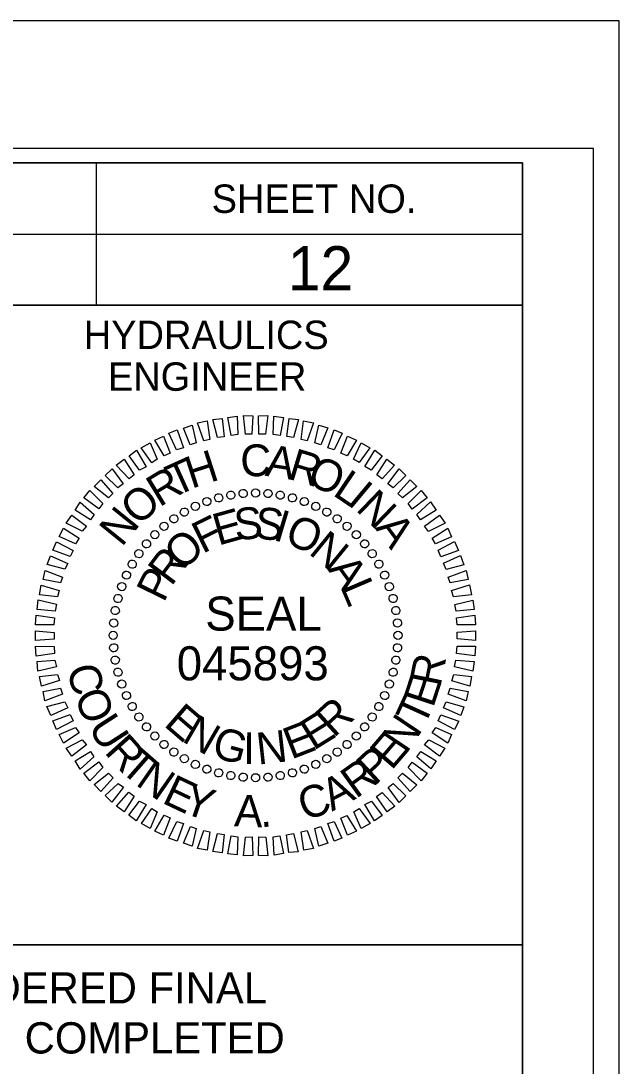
# Model space of a CAD drawing. Extents: x 1628636 to 1631253, y 896159 to 897520.
# Drawn here: x 1630638.2 to 1630743.5, y 897075 to 897258.9 of the extents above; entities that cross this region are included whole.
import ezdxf

# ---------------------------------------------------------------- set-up
doc = ezdxf.new("R2010")
doc.units = 0
for name, color, linetype in [('Default', 7, 'Continuous'), ('Sheet Cutting Line CELL', 7, 'Continuous'), ('Sheet Data Field CELL', 7, 'Continuous'), ('Sheet Plot Border Inside CELL', 7, 'Continuous'), ('Sheet Plot Border Outside CELL', 7, 'Continuous'), ('Sheet Profile CELL', 7, 'Continuous'), ('Sheet Profile Grid Major CELL', 7, 'Continuous'), ('Sheet Sticker Exception Certification CELL', 7, 'Continuous')]:
    doc.layers.add(name, color=color, linetype=linetype)

msp = doc.modelspace()

# ---------------------------------------------------------------- linework, layer by layer
at = {"layer": 'Default'}
for p, q in [((1630673.04, 897174.95), (1630673.04, 897174.95)), ((1630675.19, 897175.4), (1630675.19, 897175.4)), ((1630677.34, 897175.7), (1630677.34, 897175.7)), ((1630679.54, 897175.85), (1630679.54, 897175.85)), ((1630681.74, 897175.7), (1630681.74, 897175.7)), ((1630683.89, 897175.4), (1630683.89, 897175.4)), ((1630686.04, 897174.95), (1630686.04, 897174.95)), ((1630668.99, 897173.45), (1630668.99, 897173.45)), ((1630670.94, 897174.3), (1630670.94, 897174.3)), ((1630688.14, 897174.3), (1630688.14, 897174.3)), ((1630690.14, 897173.45), (1630690.14, 897173.45)), ((1630665.19, 897171.25), (1630665.19, 897171.25)), ((1630667.04, 897172.45), (1630667.04, 897172.45)), ((1630692.09, 897172.45), (1630692.09, 897172.45)), ((1630693.89, 897171.3), (1630693.89, 897171.3)), ((1630663.39, 897170), (1630663.39, 897170)), ((1630695.69, 897169.95), (1630695.69, 897169.95)), ((1630661.79, 897168.45), (1630661.79, 897168.45)), ((1630697.24, 897168.5), (1630697.24, 897168.5)), ((1630660.29, 897166.9), (1630660.29, 897166.9)), ((1630698.79, 897166.85), (1630698.79, 897166.85)), ((1630658.99, 897165.1), (1630658.99, 897165.1)), ((1630700.04, 897165.1), (1630700.04, 897165.1)), ((1630657.79, 897163.25), (1630657.79, 897163.25)), ((1630701.24, 897163.25), (1630701.24, 897163.25)), ((1630656.79, 897161.3), (1630656.79, 897161.3)), ((1630702.24, 897161.3), (1630702.24, 897161.3)), ((1630655.94, 897159.3), (1630655.94, 897159.3)), ((1630703.09, 897159.3), (1630703.09, 897159.3)), ((1630655.29, 897157.25), (1630655.29, 897157.25)), ((1630703.74, 897157.25), (1630703.74, 897157.25)), ((1630654.84, 897155.1), (1630654.84, 897155.1)), ((1630704.19, 897155.05), (1630704.19, 897155.05)), ((1630654.54, 897152.95), (1630654.54, 897152.95)), ((1630704.49, 897152.9), (1630704.49, 897152.9)), ((1630654.44, 897150.75), (1630654.44, 897150.75)), ((1630704.64, 897150.7), (1630704.64, 897150.7)), ((1630654.59, 897148.55), (1630654.59, 897148.55)), ((1630704.54, 897148.5), (1630704.54, 897148.5)), ((1630654.89, 897146.4), (1630654.89, 897146.4)), ((1630704.24, 897146.4), (1630704.24, 897146.4)), ((1630655.34, 897144.25), (1630655.34, 897144.25)), ((1630703.74, 897144.2), (1630703.74, 897144.2)), ((1630655.99, 897142.15), (1630655.99, 897142.15)), ((1630703.09, 897142.15), (1630703.09, 897142.15)), ((1630656.84, 897140.15), (1630656.84, 897140.15)), ((1630702.29, 897140.15), (1630702.29, 897140.15)), ((1630657.84, 897138.2), (1630657.84, 897138.2)), ((1630701.29, 897138.2), (1630701.29, 897138.2)), ((1630659.04, 897136.35), (1630659.04, 897136.35)), ((1630700.09, 897136.35), (1630700.09, 897136.35)), ((1630660.29, 897134.6), (1630660.29, 897134.6)), ((1630698.74, 897134.6), (1630698.74, 897134.6)), ((1630661.79, 897133), (1630661.79, 897133)), ((1630697.29, 897133), (1630697.29, 897133)), ((1630663.39, 897131.5), (1630663.39, 897131.5)), ((1630695.64, 897131.5), (1630695.64, 897131.5)), ((1630665.14, 897130.2), (1630665.14, 897130.2)), ((1630666.99, 897129), (1630666.99, 897129)), ((1630692.09, 897129), (1630692.09, 897129)), ((1630693.89, 897130.25), (1630693.89, 897130.25)), ((1630668.94, 897128), (1630668.94, 897128)), ((1630670.94, 897127.15), (1630670.94, 897127.15)), ((1630688.09, 897127.15), (1630688.09, 897127.15)), ((1630690.09, 897128), (1630690.09, 897128)), ((1630673.04, 897126.5), (1630673.04, 897126.5)), ((1630675.19, 897126.05), (1630675.19, 897126.05)), ((1630677.34, 897125.75), (1630677.34, 897125.75)), ((1630679.49, 897125.65), (1630679.49, 897125.65)), ((1630681.69, 897125.8), (1630681.69, 897125.8)), ((1630683.89, 897126.05), (1630683.89, 897126.05)), ((1630686.04, 897126.5), (1630686.04, 897126.5))]:
    msp.add_line(p, q, dxfattribs=at)
for points in [[(1630668.04, 897184.3), (1630666.84, 897187.25), (1630668.39, 897187.75), (1630669.09, 897184.65)], [(1630670.44, 897185), (1630669.34, 897188.15), (1630671.04, 897188.5), (1630671.49, 897185.25)], [(1630672.84, 897185.6), (1630671.99, 897188.75), (1630673.64, 897188.95), (1630674.04, 897185.7)], [(1630675.24, 897185.95), (1630674.64, 897189.1), (1630676.29, 897189.35), (1630676.44, 897186.1)], [(1630677.74, 897186.2), (1630677.39, 897189.45), (1630679.04, 897189.4), (1630678.89, 897186.2)], [(1630680.09, 897186.2), (1630680.04, 897189.4), (1630681.69, 897189.45), (1630681.29, 897186.2)], [(1630682.64, 897186.1), (1630682.74, 897189.35), (1630684.44, 897189.1), (1630683.84, 897185.95)], [(1630685.04, 897185.75), (1630685.44, 897188.95), (1630687.09, 897188.75), (1630686.24, 897185.6)], [(1630687.59, 897185.25), (1630687.99, 897188.5), (1630689.74, 897188.15), (1630688.64, 897185)], [(1630689.99, 897184.65), (1630690.64, 897187.75), (1630692.24, 897187.3), (1630691.04, 897184.3)], [(1630663.44, 897182.35), (1630661.79, 897185.15), (1630663.34, 897185.85), (1630664.54, 897182.85)], [(1630665.64, 897183.45), (1630664.29, 897186.35), (1630665.74, 897186.95), (1630666.84, 897183.8)], [(1630692.24, 897183.8), (1630693.34, 897186.95), (1630694.79, 897186.35), (1630693.39, 897183.45)], [(1630694.54, 897182.85), (1630695.69, 897185.85), (1630697.29, 897185.15), (1630695.64, 897182.35)], [(1630661.29, 897181.15), (1630659.39, 897183.8), (1630660.99, 897184.65), (1630662.24, 897181.75)], [(1630696.79, 897181.75), (1630698.09, 897184.65), (1630699.64, 897183.8), (1630697.79, 897181.2)], [(1630659.14, 897179.85), (1630657.29, 897182.35), (1630658.59, 897183.35), (1630660.29, 897180.45)], [(1630698.79, 897180.5), (1630700.54, 897183.35), (1630701.84, 897182.35), (1630699.89, 897179.85)], [(1630657.29, 897178.3), (1630655.04, 897180.7), (1630656.39, 897181.75), (1630658.19, 897179)], [(1630700.89, 897179), (1630702.64, 897181.75), (1630703.99, 897180.7), (1630701.84, 897178.3)], [(1630655.29, 897176.75), (1630653.09, 897178.9), (1630654.29, 897180.1), (1630656.24, 897177.45)], [(1630702.79, 897177.45), (1630704.79, 897180.1), (1630705.99, 897178.9), (1630703.74, 897176.75)], [(1630653.69, 897174.95), (1630651.14, 897176.95), (1630652.34, 897178.15), (1630654.44, 897175.75)], [(1630704.59, 897175.75), (1630706.74, 897178.15), (1630707.94, 897176.95), (1630705.39, 897174.95)], [(1630651.99, 897173.05), (1630649.34, 897174.95), (1630650.39, 897176.25), (1630652.69, 897173.95)], [(1630706.39, 897173.95), (1630708.69, 897176.25), (1630709.74, 897174.95), (1630707.09, 897173)], [(1630650.49, 897171.1), (1630647.79, 897172.8), (1630648.69, 897174.2), (1630651.14, 897172.05)], [(1630707.94, 897172.05), (1630710.34, 897174.25), (1630711.29, 897172.8), (1630708.54, 897171.1)], [(1630649.04, 897169.1), (1630646.24, 897170.5), (1630647.19, 897171.95), (1630649.79, 897170)], [(1630709.24, 897170), (1630711.89, 897171.95), (1630712.89, 897170.5), (1630709.99, 897169.05)], [(1630647.84, 897166.9), (1630644.99, 897168.15), (1630645.74, 897169.65), (1630648.49, 897167.85)], [(1630710.59, 897167.9), (1630713.34, 897169.65), (1630714.04, 897168.1), (1630711.19, 897166.9)], [(1630646.94, 897164.65), (1630643.84, 897165.75), (1630644.54, 897167.25), (1630647.44, 897165.7)], [(1630711.64, 897165.75), (1630714.54, 897167.3), (1630715.24, 897165.7), (1630712.14, 897164.6)], [(1630645.99, 897162.4), (1630642.89, 897163.25), (1630643.44, 897164.75), (1630646.49, 897163.4)], [(1630712.59, 897163.45), (1630715.59, 897164.8), (1630716.19, 897163.2), (1630713.09, 897162.35)], [(1630645.24, 897160), (1630642.14, 897160.6), (1630642.49, 897162.2), (1630645.59, 897161)], [(1630713.44, 897161), (1630716.59, 897162.2), (1630716.94, 897160.6), (1630713.79, 897160)], [(1630644.69, 897157.55), (1630641.54, 897157.9), (1630641.84, 897159.6), (1630644.99, 897158.65)], [(1630714.04, 897158.65), (1630717.19, 897159.65), (1630717.54, 897157.9), (1630714.39, 897157.55)], [(1630644.29, 897155.05), (1630641.09, 897155.3), (1630641.29, 897157), (1630644.54, 897156.25)], [(1630714.59, 897156.2), (1630717.79, 897156.95), (1630717.99, 897155.3), (1630714.84, 897155.05)], [(1630644.04, 897152.6), (1630640.79, 897152.6), (1630640.94, 897154.3), (1630644.14, 897153.85)], [(1630714.89, 897153.85), (1630718.14, 897154.35), (1630718.24, 897152.65), (1630714.99, 897152.65)], [(1630644.09, 897150.1), (1630640.84, 897149.85), (1630640.79, 897151.55), (1630644.09, 897151.3)], [(1630714.99, 897151.35), (1630718.24, 897151.6), (1630718.24, 897149.9), (1630714.99, 897150.15)], [(1630644.14, 897147.6), (1630640.94, 897147.1), (1630640.84, 897148.85), (1630644.09, 897148.8)], [(1630714.99, 897148.85), (1630718.24, 897148.85), (1630718.14, 897147.15), (1630714.89, 897147.6)], [(1630644.54, 897145.25), (1630641.24, 897144.45), (1630641.09, 897146.15), (1630644.24, 897146.4)], [(1630714.79, 897146.4), (1630717.99, 897146.15), (1630717.79, 897144.5), (1630714.54, 897145.25)], [(1630645.04, 897142.85), (1630641.89, 897141.85), (1630641.54, 897143.55), (1630644.69, 897143.9)], [(1630714.44, 897143.9), (1630717.54, 897143.55), (1630717.24, 897141.85), (1630714.09, 897142.8)], [(1630645.59, 897140.45), (1630642.44, 897139.25), (1630642.14, 897140.9), (1630645.24, 897141.5)], [(1630713.79, 897141.5), (1630716.94, 897140.9), (1630716.59, 897139.25), (1630713.44, 897140.45)], [(1630646.49, 897138), (1630643.49, 897136.65), (1630642.84, 897138.25), (1630645.99, 897139.1)], [(1630713.09, 897139.05), (1630716.19, 897138.2), (1630715.64, 897136.7), (1630712.59, 897138.05)], [(1630647.44, 897135.75), (1630644.49, 897134.2), (1630643.84, 897135.75), (1630646.94, 897136.85)], [(1630712.14, 897136.8), (1630715.29, 897135.7), (1630714.54, 897134.2), (1630711.64, 897135.75)], [(1630648.49, 897133.6), (1630645.74, 897131.8), (1630644.99, 897133.35), (1630647.84, 897134.55)], [(1630711.24, 897134.55), (1630714.04, 897133.35), (1630713.34, 897131.8), (1630710.59, 897133.6)], [(1630649.79, 897131.5), (1630647.19, 897129.5), (1630646.24, 897130.95), (1630649.04, 897132.4)], [(1630710.04, 897132.4), (1630712.84, 897130.95), (1630711.89, 897129.5), (1630709.29, 897131.5)], [(1630651.09, 897129.4), (1630648.69, 897127.25), (1630647.79, 897128.7), (1630650.49, 897130.35)], [(1630708.59, 897130.35), (1630711.29, 897128.7), (1630710.39, 897127.3), (1630707.94, 897129.4)], [(1630652.64, 897127.5), (1630650.39, 897125.2), (1630649.34, 897126.5), (1630651.94, 897128.5)], [(1630707.09, 897128.45), (1630709.74, 897126.5), (1630708.69, 897125.2), (1630706.39, 897127.5)], [(1630654.49, 897125.7), (1630652.29, 897123.3), (1630651.14, 897124.55), (1630653.64, 897126.5)], [(1630705.39, 897126.5), (1630707.94, 897124.5), (1630706.74, 897123.3), (1630704.59, 897125.7)], [(1630656.29, 897124.05), (1630654.24, 897121.4), (1630653.09, 897122.6), (1630655.34, 897124.7)], [(1630703.74, 897124.7), (1630705.99, 897122.55), (1630704.79, 897121.35), (1630702.84, 897124)], [(1630658.19, 897122.5), (1630656.44, 897119.75), (1630655.09, 897120.75), (1630657.24, 897123.2)], [(1630660.29, 897121), (1630658.54, 897118.15), (1630657.24, 897119.15), (1630659.14, 897121.6)], [(1630699.94, 897121.6), (1630701.79, 897119.1), (1630700.49, 897118.15), (1630698.79, 897121)], [(1630701.79, 897123.15), (1630704.04, 897120.75), (1630702.69, 897119.7), (1630700.84, 897122.45)], [(1630662.24, 897119.7), (1630660.99, 897116.8), (1630659.44, 897117.7), (1630661.29, 897120.3)], [(1630697.74, 897120.3), (1630699.69, 897117.65), (1630698.14, 897116.8), (1630696.84, 897119.7)], [(1630664.54, 897118.65), (1630663.34, 897115.6), (1630661.79, 897116.3), (1630663.44, 897119.15)], [(1630666.84, 897117.7), (1630665.74, 897114.55), (1630664.29, 897115.1), (1630665.69, 897118.05)], [(1630693.39, 897118.05), (1630694.74, 897115.1), (1630693.34, 897114.55), (1630692.24, 897117.7)], [(1630695.59, 897119.1), (1630697.29, 897116.3), (1630695.74, 897115.6), (1630694.54, 897118.6)], [(1630669.09, 897116.8), (1630668.39, 897113.7), (1630666.84, 897114.2), (1630668.09, 897117.15)], [(1630671.49, 897116.2), (1630671.04, 897113), (1630669.34, 897113.3), (1630670.44, 897116.45)], [(1630674.04, 897115.75), (1630673.64, 897112.5), (1630671.99, 897112.75), (1630672.84, 897115.9)], [(1630686.24, 897115.9), (1630687.04, 897112.7), (1630685.39, 897112.55), (1630684.99, 897115.7)], [(1630688.64, 897116.45), (1630689.74, 897113.3), (1630688.04, 897112.95), (1630687.59, 897116.2)], [(1630691.04, 897117.15), (1630692.24, 897114.2), (1630690.64, 897113.7), (1630689.94, 897116.8)], [(1630676.44, 897115.35), (1630676.29, 897112.15), (1630674.64, 897112.35), (1630675.24, 897115.5)], [(1630678.94, 897115.3), (1630679.04, 897112.05), (1630677.39, 897112), (1630677.74, 897115.25)], [(1630681.34, 897115.25), (1630681.69, 897112), (1630680.04, 897112.05), (1630680.14, 897115.3)], [(1630683.79, 897115.5), (1630684.44, 897112.4), (1630682.79, 897112.1), (1630682.64, 897115.35)]]:
    msp.add_lwpolyline(points, close=True, dxfattribs=at)
for centre, major_axis in [((1630670.97, 897174.32), (-0.246, 0.676)), ((1630673.05, 897174.98), (-0.186, 0.695)), ((1630675.19, 897175.45), (-0.125, 0.708)), ((1630677.36, 897175.74), (-0.063, 0.717)), ((1630679.54, 897175.83), (0, 0.719)), ((1630681.72, 897175.74), (0.063, 0.717)), ((1630683.89, 897175.45), (0.125, 0.708)), ((1630686.02, 897174.98), (0.186, 0.695)), ((1630688.11, 897174.32), (0.246, 0.676)), ((1630667.01, 897172.47), (-0.36, 0.623)), ((1630668.95, 897173.48), (-0.304, 0.652)), ((1630690.13, 897173.48), (0.304, 0.652)), ((1630692.07, 897172.47), (0.36, 0.623)), ((1630665.17, 897171.3), (-0.413, 0.589)), ((1630693.91, 897171.3), (0.413, 0.589)), ((1630661.82, 897168.49), (-0.509, 0.509)), ((1630663.43, 897169.97), (-0.462, 0.551)), ((1630695.64, 897169.97), (0.462, 0.551)), ((1630697.26, 897168.49), (0.509, 0.509)), ((1630660.35, 897166.88), (-0.551, 0.462)), ((1630698.73, 897166.88), (0.551, 0.462)), ((1630659.02, 897165.15), (-0.589, 0.413)), ((1630700.06, 897165.15), (0.589, 0.413)), ((1630657.84, 897163.3), (-0.623, 0.36)), ((1630701.24, 897163.3), (0.623, 0.36)), ((1630656.83, 897161.37), (-0.652, 0.304)), ((1630702.25, 897161.37), (0.652, 0.304)), ((1630655.99, 897159.35), (-0.676, 0.246)), ((1630703.08, 897159.35), (0.676, 0.246)), ((1630655.34, 897157.26), (-0.695, 0.186)), ((1630703.74, 897157.26), (0.695, 0.186)), ((1630654.86, 897155.13), (-0.708, 0.125)), ((1630704.21, 897155.13), (0.708, 0.125)), ((1630654.58, 897152.96), (-0.717, 0.063)), ((1630704.5, 897152.96), (0.717, 0.063)), ((1630654.48, 897150.78), (-0.719, 0)), ((1630704.59, 897150.78), (0.719, 0)), ((1630654.58, 897148.59), (-0.717, -0.063)), ((1630704.5, 897148.59), (0.717, -0.063)), ((1630654.86, 897146.43), (-0.708, -0.125)), ((1630704.21, 897146.43), (0.708, -0.125)), ((1630655.34, 897144.29), (-0.695, -0.186)), ((1630703.74, 897144.29), (0.695, -0.186)), ((1630655.99, 897142.21), (-0.676, -0.246)), ((1630703.08, 897142.21), (0.676, -0.246)), ((1630656.83, 897140.19), (-0.652, -0.304)), ((1630702.25, 897140.19), (0.652, -0.304)), ((1630657.84, 897138.25), (-0.623, -0.36)), ((1630701.24, 897138.25), (0.623, -0.36)), ((1630659.02, 897136.41), (-0.589, -0.413)), ((1630700.06, 897136.41), (0.589, -0.413)), ((1630660.35, 897134.67), (-0.551, -0.462)), ((1630698.73, 897134.67), (0.551, -0.462)), ((1630661.82, 897133.06), (-0.509, -0.509)), ((1630697.26, 897133.06), (0.509, -0.509)), ((1630663.43, 897131.58), (-0.462, -0.551)), ((1630665.17, 897130.25), (-0.413, -0.589)), ((1630693.91, 897130.25), (0.413, -0.589)), ((1630695.64, 897131.58), (0.462, -0.551)), ((1630667.01, 897129.08), (-0.36, -0.623)), ((1630668.95, 897128.07), (-0.304, -0.652)), ((1630690.13, 897128.07), (0.304, -0.652)), ((1630692.07, 897129.08), (0.36, -0.623)), ((1630670.97, 897127.23), (-0.246, -0.676)), ((1630673.05, 897126.58), (-0.186, -0.695)), ((1630686.02, 897126.58), (0.186, -0.695)), ((1630688.11, 897127.23), (0.246, -0.676)), ((1630675.19, 897126.1), (-0.125, -0.708)), ((1630677.36, 897125.82), (-0.063, -0.717)), ((1630679.54, 897125.72), (0, -0.719)), ((1630681.72, 897125.82), (0.063, -0.717)), ((1630683.89, 897126.1), (0.125, -0.708))]:
    msp.add_ellipse(centre, major_axis=major_axis, ratio=0.999708, dxfattribs=at)
at = {"layer": 'Sheet Cutting Line CELL'}
msp.add_line((1630743.5, 897258.9), (1629059.5, 897258.9), dxfattribs=at)
at = {"layer": 'Sheet Plot Border Inside CELL'}
msp.add_lwpolyline([(1629072.5, 896181.35), (1630739, 896181.35), (1630739, 897236.45), (1629072.5, 897236.45)], close=True, dxfattribs=at)
at = {"layer": 'Sheet Plot Border Outside CELL'}
msp.add_lwpolyline([(1629059.5, 896158.9), (1630743.5, 896158.9), (1630743.5, 897258.9), (1629059.5, 897258.9)], close=True, dxfattribs=at)
at = {"layer": 'Sheet Profile CELL'}
for p, q in [((1630651.5, 897233.85), (1630651.5, 897208.85)), ((1630526.45, 897221.35), (1630726.5, 897221.35))]:
    msp.add_line(p, q, dxfattribs=at)
for points in [[(1630726.5, 897233.9), (1629226.5, 897233.9), (1629226.5, 896183.9), (1630726.5, 896183.9)], [(1630526.45, 897233.9), (1630726.5, 897233.9), (1630726.5, 897208.85), (1630526.45, 897208.85)], [(1630626.5, 897208.85), (1630726.5, 897208.85), (1630726.5, 897096.35), (1630626.5, 897096.35)]]:
    msp.add_lwpolyline(points, close=True, dxfattribs=at)
at = {"layer": 'Sheet Profile Grid Major CELL'}
msp.add_lwpolyline([(1630676.5, 897072.85), (1630676.5, 896733.9), (1630726.5, 896733.9), (1630726.5, 897083.9)], dxfattribs=at)
at = {"layer": 'Sheet Sticker Exception Certification CELL'}
for p, q in [((1630526.45, 897096.35), (1630726.49, 897096.35)), ((1630526.45, 897096.35), (1630726.49, 897096.35)), ((1630726.49, 897096.33), (1630726.49, 897072.83)), ((1630726.49, 897096.33), (1630726.49, 897072.83))]:
    msp.add_line(p, q, dxfattribs=at)

# ---------------------------------------------------------------- texts
at = {"layer": 'Default'}
for s, height, rotation, p in [('C', 5.6, 359.8514, (1630676.84, 897178.79)), ('A', 5.6, 351.2223, (1630681.08, 897178.88)), ('H', 5.6, 17.9268, (1630668.26, 897176.56)), ('R', 5.6, 343.1874, (1630685, 897178.4)), ('T', 5.6, 24.3275, (1630665.45, 897175.14)), ('O', 5.6, 336.242, (1630688.3, 897177.54)), ('R', 5.6, 31.2729, (1630662.61, 897173.25)), ('L', 5.6, 326.0282, (1630692.92, 897175.56)), ('O', 5.6, 41.4867, (1630658.88, 897169.89)), ('I', 5.6, 320.0485, (1630695.43, 897174.04)), ('N', 5.6, 316.0496, (1630697.02, 897172.87)), ('N', 5.6, 51.032, (1630655.99, 897166.19)), ('E', 5.6, 15.6529, (1630672.96, 897166.54)), ('S', 5.6, 5.0487, (1630675.99, 897167.49)), ('S', 5.6, 354.1866, (1630679.21, 897167.87)), ('F', 5.6, 26.1465, (1630670.19, 897165.08)), ('I', 5.6, 343.3245, (1630682.44, 897167.63)), ('O', 5.6, 336.6634, (1630684.39, 897167.18)), ('A', 5.6, 306.5043, (1630700.45, 897169.67)), ('O', 5.6, 42.0574, (1630666.62, 897161.96)), ('N', 5.6, 320.7526, (1630688.71, 897165.23)), ('R', 5.6, 53.1038, (1630664.7, 897159.27)), ('A', 5.6, 305.8367, (1630692.14, 897162.38)), ('P', 5.6, 63.7079, (1630663.39, 897156.39)), ('L', 5.6, 293.1688, (1630694.39, 897159.34)), ('SEAL', 5.992, 360, (1630670.69, 897151.61)), ('045893', 5.994, 360, (1630665.67, 897142.86)), ('R', 5.6, 78.5969, (1630712.06, 897141.59)), ('C', 5.6, 284.0401, (1630646.3, 897145.02)), ('E', 5.6, 71.9487, (1630710.78, 897137.89)), ('O', 5.6, 292.6692, (1630647.53, 897140.09)), ('T', 5.6, 65.548, (1630709.16, 897134.49)), ('E', 5.6, 319.2324, (1630663.21, 897134.97)), ('R', 5.6, 42.4535, (1630693.29, 897132.63)), ('U', 5.6, 302.883, (1630649.93, 897134.58)), ('N', 5.6, 329.8366, (1630666.39, 897132.23)), ('E', 5.6, 31.8494, (1630689.72, 897130.41)), ('N', 5.6, 56.0027, (1630706.05, 897129.8)), ('G', 5.6, 344.7525, (1630671.6, 897129.46)), ('E', 5.6, 21.2452, (1630685.81, 897128.89)), ('R', 5.6, 311.7969, (1630652.79, 897130.18)), ('I', 5.6, 359.6683, (1630677.34, 897128.12)), ('N', 5.6, 6.3293, (1630679.98, 897128.02)), ('E', 5.6, 49.3544, (1630703.45, 897126.88)), ('T', 5.6, 318.7423, (1630655.47, 897127.1)), ('P', 5.6, 42.7062, (1630700.53, 897124.27)), ('N', 5.6, 325.143, (1630658.25, 897124.56)), ('R', 5.6, 35.7608, (1630697.18, 897121.93)), ('E', 5.6, 334.6883, (1630662.89, 897121.38)), ('A', 5.6, 27.7259, (1630692.98, 897119.75)), ('Y', 5.6, 341.3366, (1630666.4, 897119.65)), ('C', 5.6, 19.0968, (1630688.18, 897118.09)), ('A', 5.6, 357.753, (1630675.71, 897117.19)), ('.', 5.6, 5.7878, (1630680.44, 897116.98))]:
    msp.add_text(s, height=height, rotation=rotation, dxfattribs=at).set_placement(p)
at = {"layer": 'Sheet Data Field CELL'}
msp.add_text('12', height=7.75, dxfattribs=at).set_placement((1630685.2, 897211.51))
at = {"layer": 'Sheet Profile CELL'}
for s, p in [('SHEET NO.', (1630671.81, 897225.11)), ('HYDRAULICS', (1630649.31, 897201.16)), ('ENGINEER', (1630653.56, 897193.81))]:
    msp.add_text(s, height=5, dxfattribs=at).set_placement(p)
at = {"layer": 'Sheet Sticker Exception Certification CELL'}
for s, p in [('DOCUMENT NOT CONSIDERED FINAL', (1630547.52, 897086)), ('DOCUMENT NOT CONSIDERED FINAL', (1630547.52, 897086)), ('UNLESS ALL SIGNATURES COMPLETED', (1630542.45, 897077.2)), ('UNLESS ALL SIGNATURES COMPLETED', (1630542.45, 897077.2))]:
    msp.add_text(s, height=5.5, dxfattribs=at).set_placement(p)

doc.saveas('drawing.dxf')
